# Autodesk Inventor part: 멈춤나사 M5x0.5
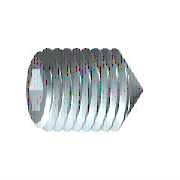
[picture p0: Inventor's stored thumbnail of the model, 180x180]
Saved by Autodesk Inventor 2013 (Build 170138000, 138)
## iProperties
Company: 한국ATC센터
IsCustomPart: 1
Created: 2014-10
Part Number: 멈춤나사 M5x0.5
Material: 강철, 연강
Description: 6각 소켓 머리 없는 멈춤 나사
Document SubType Name: Modeling
Standard: KS B 1028
Designer: 한국ATC센터
Standards Organization: KS
Language: ko-KR
Size Designation: 원추점 M5x10
Categories: <MemberInstance><Categories><Category DisplayName="조임쇠" InternalName="e4da775c-781d-43d5-af7c-5136215cf5a6" Mnemonic="FSTN"><Category DisplayName="볼트" InternalN
Density: 7.86 g/cm^3
Mass: 1.16912 g
Surface Area: 1.91683 cm^2
Volume: 0.148743 cm^3
Author: KYOUNG IL JANG
Revision Number: 1
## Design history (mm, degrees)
sketch "스케치1"
  geometry: L1 (0, 0)-(6.167, 0); L2 (10, 1.443)-(10, 2.5); L3 (10, 2.5)-(0, 2.5); L4 (10, 1.443)-(7, 1.443); L5 (7, 1.443)-(6.167, 0); L6 (0, -0.5)-(0, 3) reference; L7 (0, 2.5)-(0, 0)
  constraints: 13 end point, 3 parallel, 1 collinear, 1 perpendicular, 1 point on line
  dimensions: "d0" = 3 distance of L2.start L4.end (= INTI); "d1" = 60 deg angle of L5 L1; "d2" = 5 diameter of L3 L1 (= NND); "d3" = 2.88675 diameter of L4 L1 (= 1.1547 x SW); "d5" = 10 distance from line of L2 L3.end (= NLG)
revolve "본체" sketch "스케치1" stored, may be unused: angle "d6" = 90 deg
sketch "스케치2"
  geometry: L1 (-0.722, 1.25)-(0.722, 1.25); L2 (0.722, 1.25)-(1.443, 0); L3 (1.443, 0)-(0.722, -1.25); L4 (0.722, -1.25)-(-0.722, -1.25); L5 (-0.722, -1.25)-(-1.443, 0); L6 (-1.443, 0)-(-0.722, 1.25); 3 further points
  constraints: 12 end point, 1 coincident, 1 horizontal, 13 other
extrude "슬롯" join sketch "스케치2" taper "d7" = 0 deg; stored distance "d21" = 10
workaxis "Work Axis1"
workplane "Work Plane1"
body "Solid1"
feature "스레드" dims "d12" = 10 (= NLG), "d13" = 0
chamfer "모따기1" distance "d8" = 2.25 (computed from NND, SPD, FAWI); stored, may be unused: angle "d9" = 45 deg (= FAWI), second distance "d34" = 2.25 (computed from NND, SPD, FAWI)
chamfer "모따기2" distance "d10" = 0.49076 (= -0.5 x GD1 + 0.5 x NND); stored, may be unused: angle "d11" = 45 deg (= FAWI), second distance "d35" = 0.49076 (= -0.5 x GD1 + 0.5 x NND)
other parameters: "NND" = 5 [user parameter; used in 5 equation terms], "NLG" = 10 [user parameter; used in 2 equation terms], "INTI" = 3 [user parameter; used in 1 equation term], "FAWI" = 45 deg [user parameter; used in 4 equation terms], "SW" = 2.5 [user parameter; used in 2 equation terms], "GD1" = 4.01848 (= THREADDIA - 1.2269 x PTC) [user parameter; used in 2 equation terms], "d4" = 0, "FAWI1" = 45 deg [user parameter], "SPD" = 0.5 [user parameter; used in 2 equation terms], "d36" = 0, "d37" = 0, "GUL" = 0.49076 (= 0.61345 x PTC) [user parameter], "TPU" = 12.5 (computed from PTC) [user parameter], "TOA" = 30 deg [user parameter], "THREADDIA" = 5 [user parameter; used in 1 equation term], "PTC" = 0.8 [user parameter; used in 4 equation terms], "GAL" = 0.49076 (= 0.61345 x PTC) [user parameter], "E0" = 2.8875 (= 1.155 x SW) [user parameter]
